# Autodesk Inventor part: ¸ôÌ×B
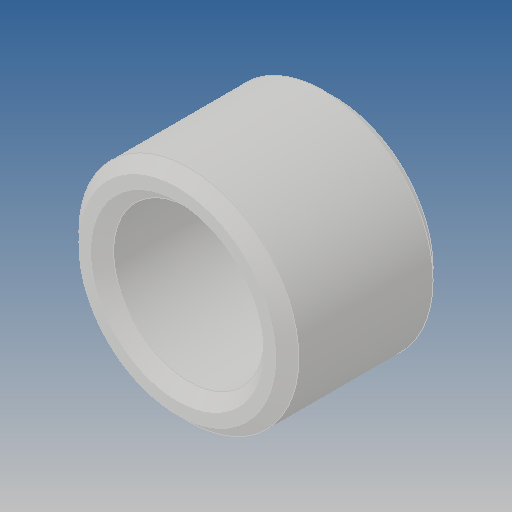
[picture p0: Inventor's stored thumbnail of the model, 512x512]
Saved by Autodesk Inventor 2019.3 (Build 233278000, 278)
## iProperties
Created: 2017-08
Part Number: ¸ôÌ×B
Material: Ogólny
Document SubType Name: Modeling
Designer: Admin
Density: 1 g/cm^3
Appearance: Domyślna
Author: Admin
Revision Number: ÈÎºÎ
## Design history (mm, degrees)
feature "ÊäÈë1"
node "Bryła1"
